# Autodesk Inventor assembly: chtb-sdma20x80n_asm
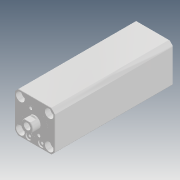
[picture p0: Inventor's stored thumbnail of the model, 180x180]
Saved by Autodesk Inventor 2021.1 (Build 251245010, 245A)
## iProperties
Created: 2018-05
Part Number: chtb-sdma20x80n_asm
Description: STEP AP214
Document SubType Name: Assembly
Designer: user
Title: chtb-sdma20x80n_asm.STEP
Revision Number: ÈÎºÎ
Sending System: SolidWorks 2016
Preprocessor: SwSTEP 2.0
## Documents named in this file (5)
- D:\Vault_2016\Projekty\Clamptek\Hydraulic\CHTB\CHTB-20\Inventor\CHTB-SDMA20x80N\chtb-sdma20x80n_asm.iam
- D:\Vault_2016\Projekty\Clamptek\Hydraulic\CHTB\CHTB-20\Inventor\CHTB-SDMA20x80N\CHTB-SDMA20X80NBT.ipt
- D:\Vault_2016\Projekty\Clamptek\Hydraulic\CHTB\CHTB-20\Inventor\CHTB-SDMA20x80N\CHTB-SDMA20X80NHSG.ipt
- D:\Vault_2016\Projekty\Clamptek\Hydraulic\CHTB\CHTB-20\Inventor\CHTB-SDMA20x80N\QG_3.ipt
- D:\Vault_2016\Projekty\Clamptek\Hydraulic\CHTB\CHTB-20\Inventor\CHTB-SDMA20x80N\socket set screw flat point_iso_ISO 4026 - M5 x 5-N.ipt
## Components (5 placed, 5 different names)
1. CHTB-SDMA20X80NBT_1
2. CHTB-SDMA20X80NHSG_2
3. QG_3_3
4. socket set screw flat point_iso_ISO 4026 - M5 x 5-N_4
5. socket set screw flat point_iso_ISO 4026 - M5 x 5-N_5
